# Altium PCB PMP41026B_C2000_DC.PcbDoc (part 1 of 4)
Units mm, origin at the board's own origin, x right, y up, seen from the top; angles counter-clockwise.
Board outline 100 x 30 mm, 4 copper layers (Top Layer, Layer2-Plane, Layer3-Plane, Bottom Layer), stack 1.565 mm thick; 260 components, 175 nets, 797 pads, 279 vias.
Unrouted connection lines stored in the file: 19.
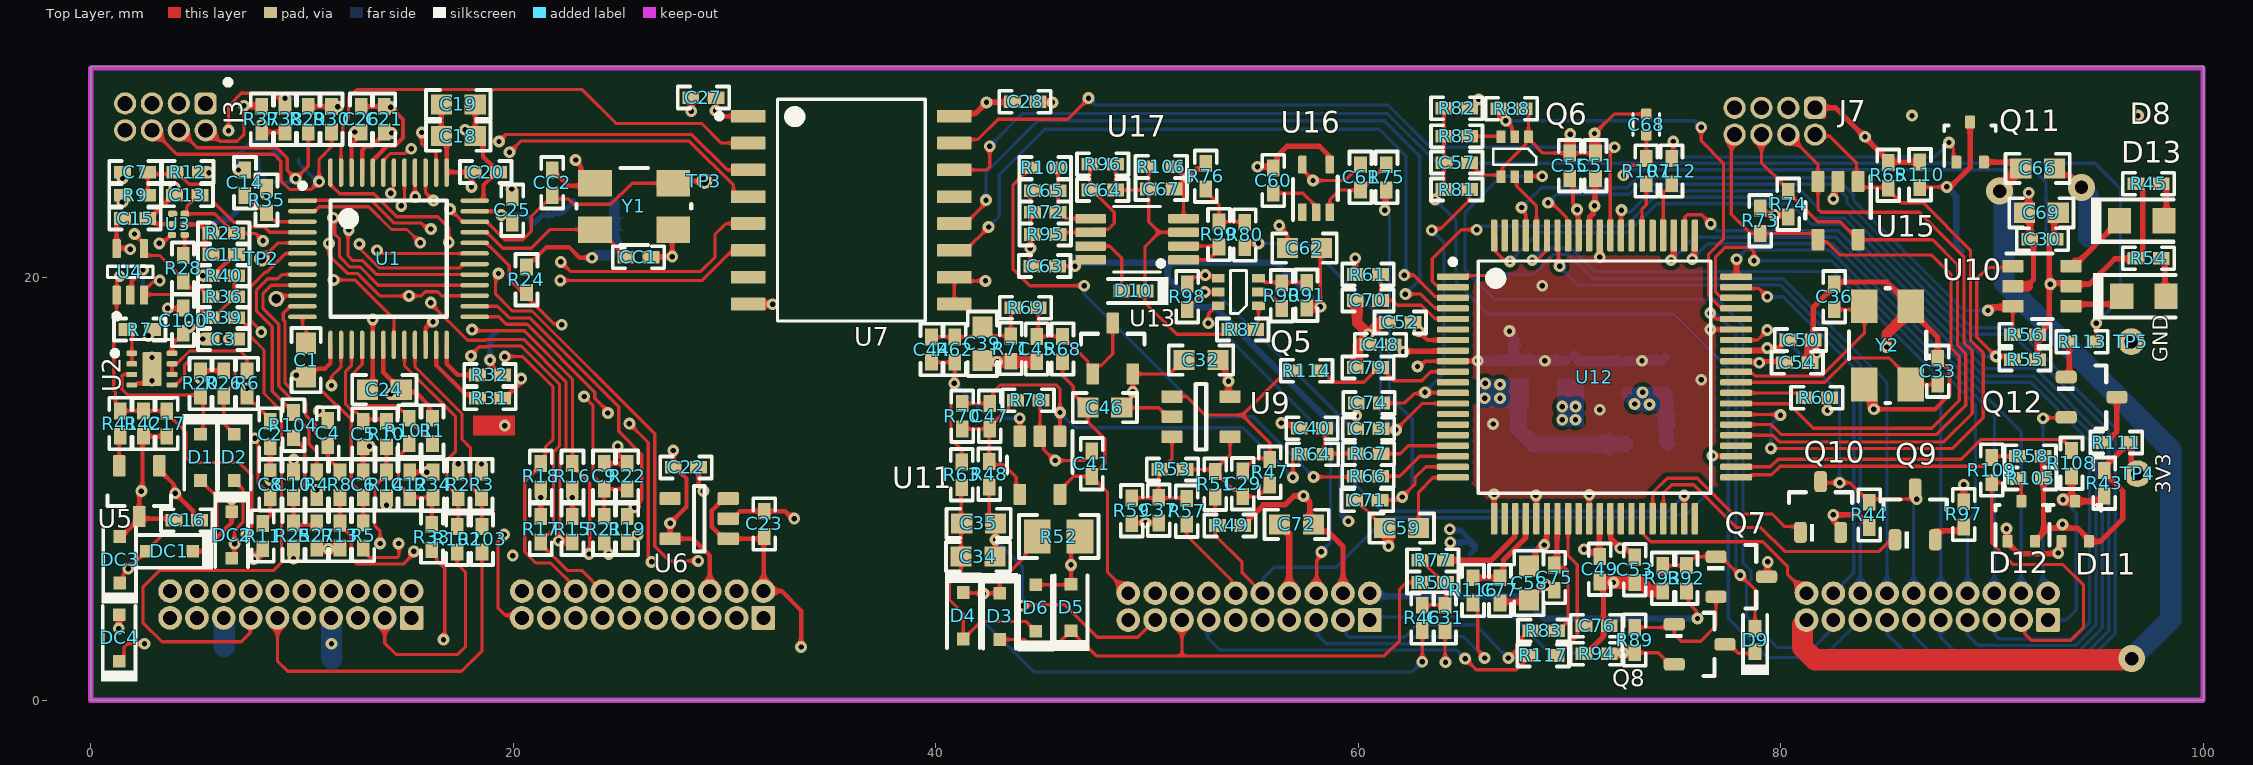
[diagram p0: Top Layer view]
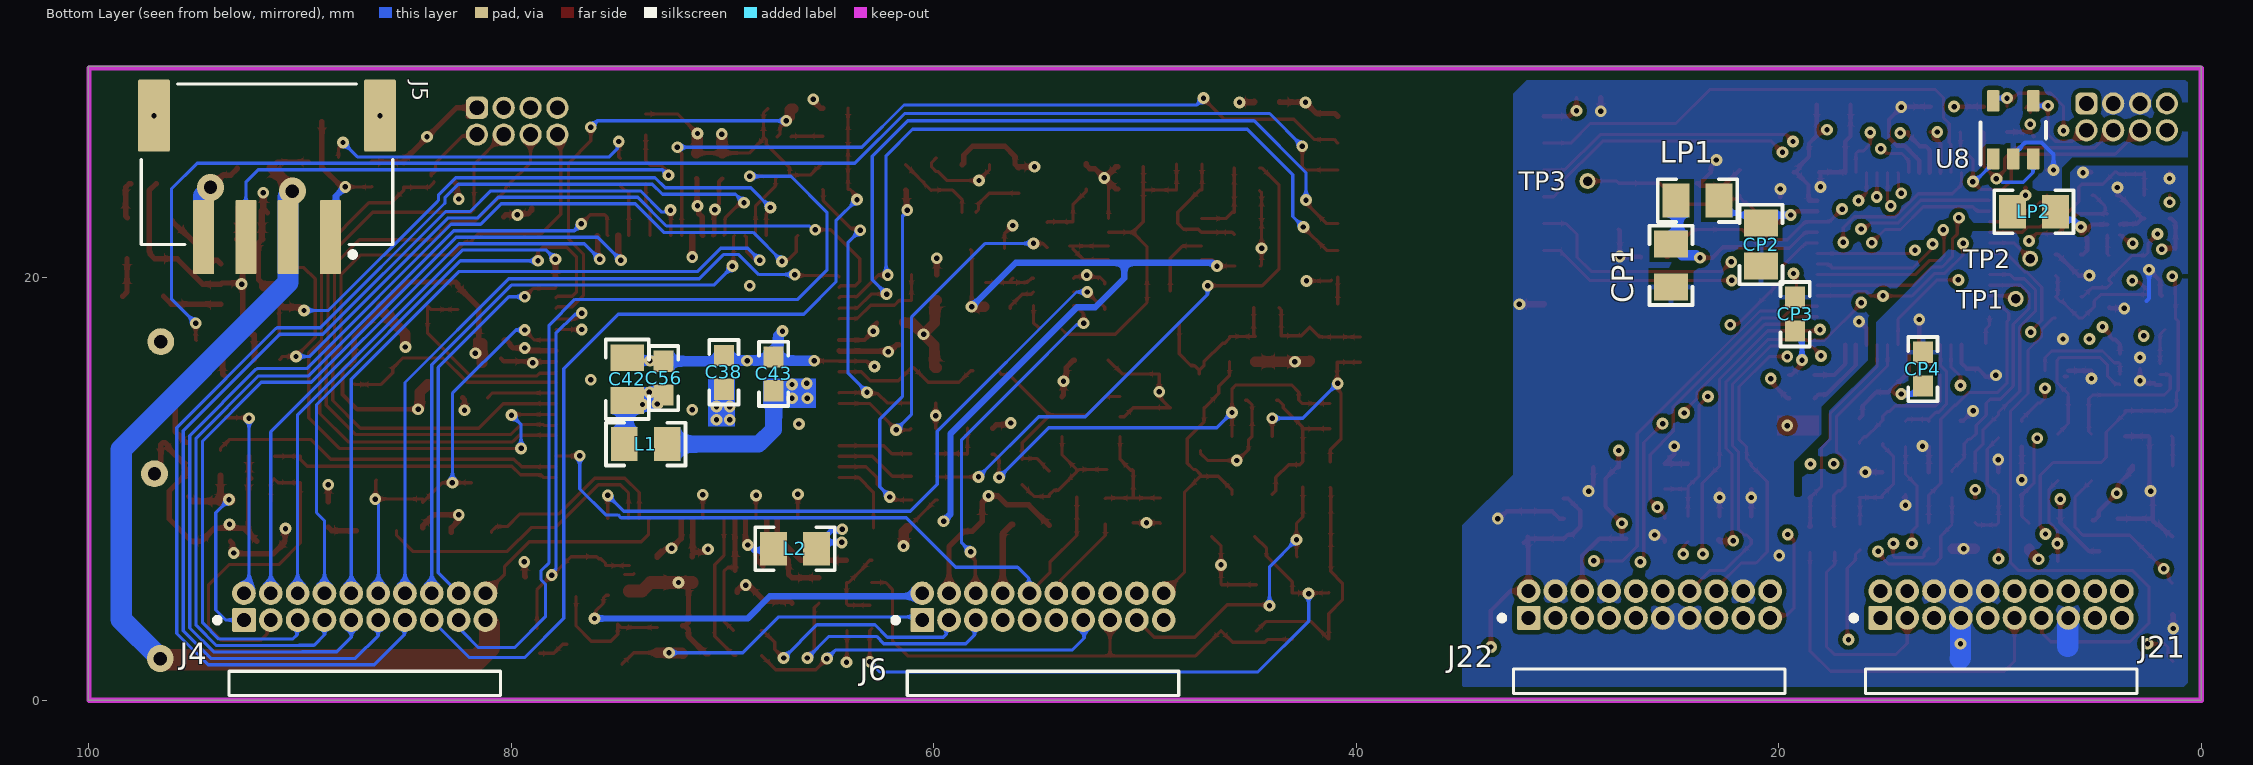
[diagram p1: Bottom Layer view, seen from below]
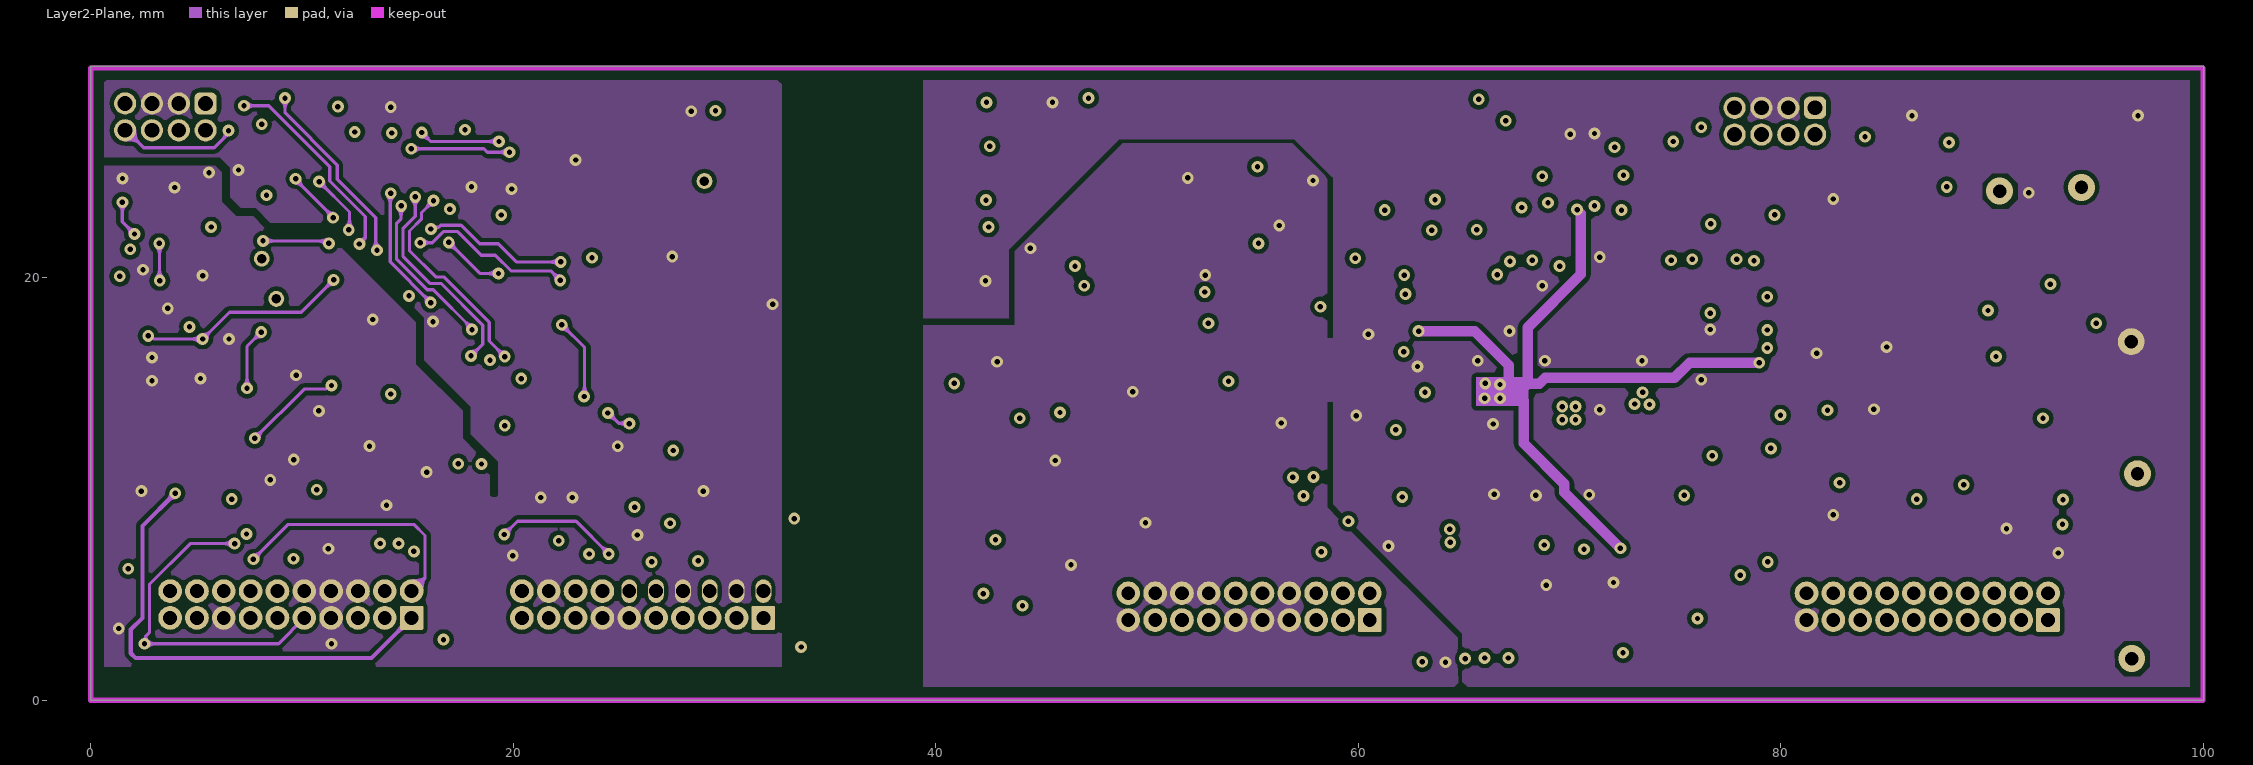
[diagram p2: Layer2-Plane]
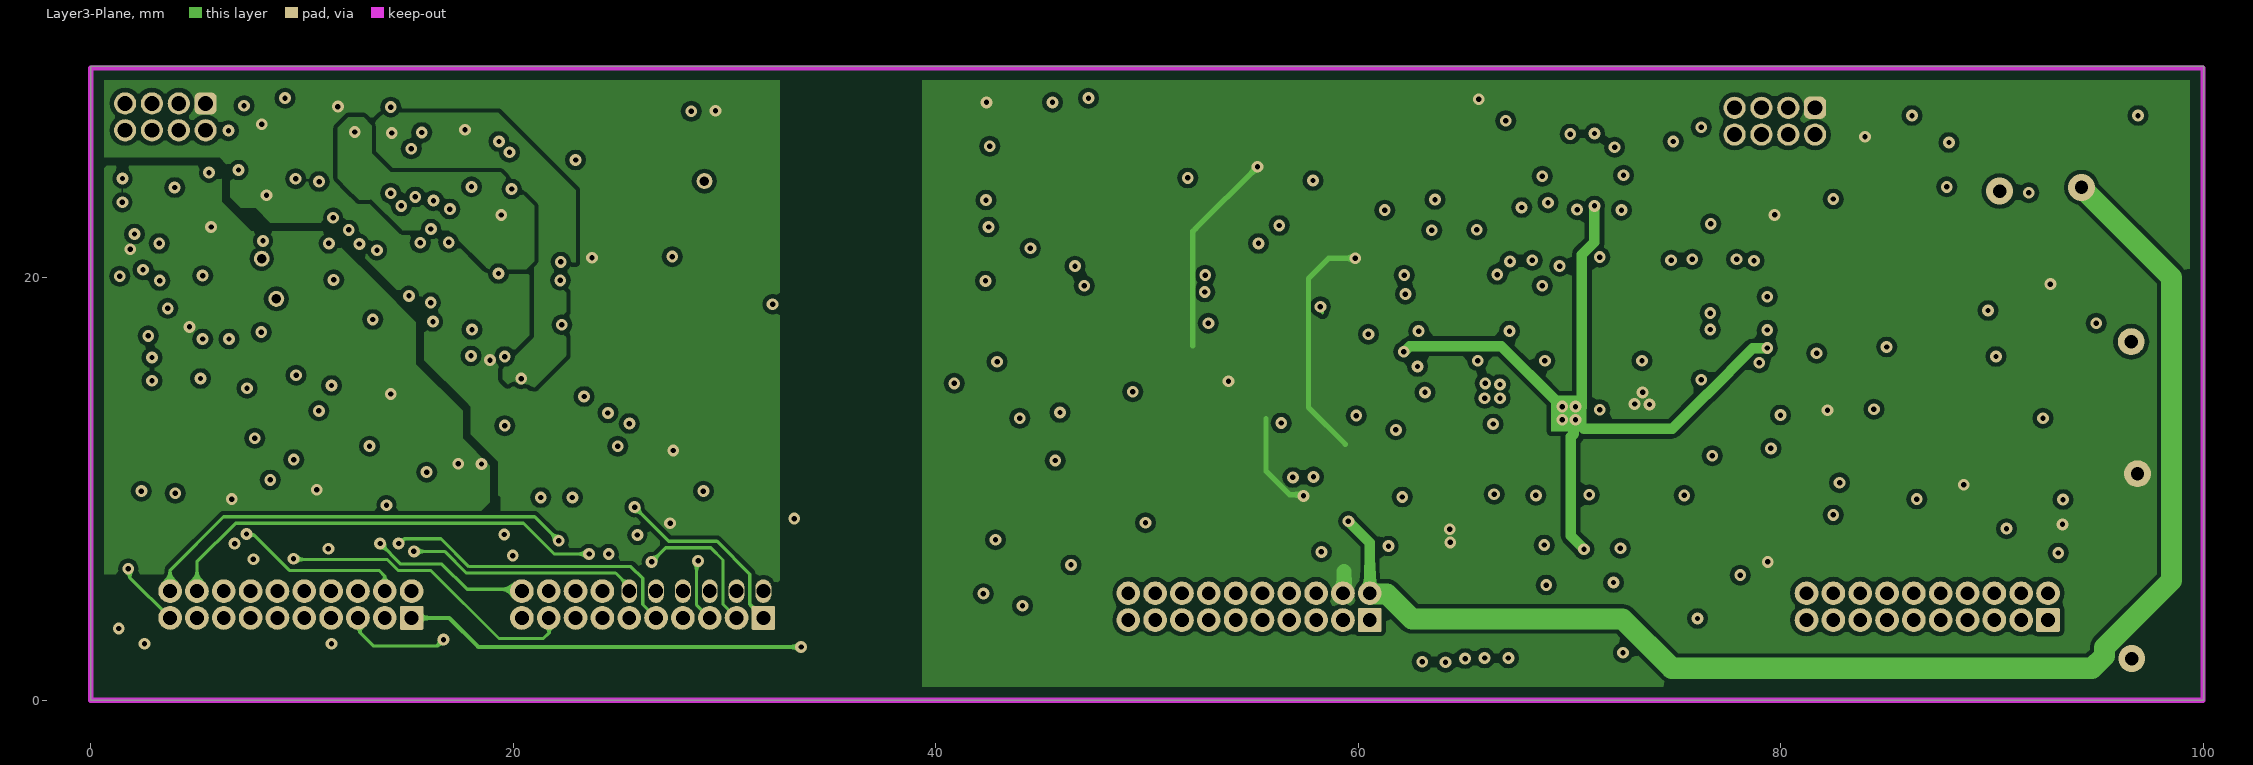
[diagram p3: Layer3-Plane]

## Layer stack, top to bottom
Top Solder: solder mask 0.0102, Solder Resist, Dk 3.5
Top Layer: signal copper 0.0356
Dielectric1: prepreg 0.2032, FR-4 High Tg, Dk 4.2
Layer2-Plane: signal copper 0.0356
Dielectric 2: core 1.016, FR-4 High Tg, Dk 4.2
Layer3-Plane: signal copper 0.0356
Dielectric 3: prepreg 0.2032, FR-4 High Tg, Dk 4.2
Bottom Layer: signal copper 0.0356
Bottom Solder: solder mask 0.0102, Solder Resist, Dk 3.5

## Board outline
0,0 0,30 100,30 100,0

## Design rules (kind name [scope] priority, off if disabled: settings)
AcuteAngle [All] p1: isadvanced=TRUE minimum=4.50000000000000E+0001 checktracksonly=FALSE
AssemblyTestPointUsage [All] p1: isadvanced=TRUE valid=2
AssemblyTestpoint [All] p1: isadvanced=TRUE testpointundercomponent=TRUE minsize=1.016 maxsize=2.54 preferedsize=1.524 minholesize=0 maxholesize=1.016 preferedholesize=0.813 testpointgrid=0.025 usegrid=TRUE gridtolerance=0 allowsidetop=TRUE allowsidebottom=TRUE
BoardOutlineClearance BoardOutlineClearance_MountingHoles [OnCopper and InComponentClass('Mounting Holes')] p1: isadvanced=TRUE gap=1 ignorepadtopadclearanceinfootprint=FALSE
BoardOutlineClearance BoardOutlineClearance_Poly [OnCopper and IsPoly] p2: isadvanced=TRUE gap=0.635 ignorepadtopadclearanceinfootprint=FALSE
BoardOutlineClearance [OnCopper and Not InComponentClass('Logo') and not InComponentClass('FiducialMark') and not InRegion(1000,500,4000,800) and not InPoly and not InComponent('J1')] p3: isadvanced=TRUE gap=1.016 ignorepadtopadclearanceinfootprint=FALSE
Clearance Clearance_Keepouts [((IsTrack Or IsArc) And Not InPoly) And IsFree and IsKeepOut vs ((IsTrack Or IsArc) And Not InPoly) And IsFree and IsKeepOut] p1: isadvanced=TRUE gap=0.152 ignorepadtopadclearanceinfootprint=FALSE except(0.178: Arc-THPad Track-THPad SMDPad-THPad THPad-THPad THPad-Via THPad-Fill THPad-Poly THPad-Region THPad-Text THPad-Hole)
Clearance Clearance_Poly [InPolygon] p2: isadvanced=TRUE gap=0.203 ignorepadtopadclearanceinfootprint=TRUE
Clearance Clearance_FiducialMark [IsKeepOut and InComponentClass('FiducialMark') vs IsPad and InComponentClass('FiducialMark')] p3: isadvanced=TRUE gap=0 ignorepadtopadclearanceinfootprint=FALSE
Clearance Clearance_1 [(ExistsOnLayer('Layer2-Plane') Or ExistsOnLayer('Layer3-Plane')) vs (ExistsOnLayer('Layer2-Plane') Or ExistsOnLayer('Layer3-Plane'))] p4: gap=0.152 ignorepadtopadclearanceinfootprint=TRUE except(0.178: Arc-THPad Track-THPad SMDPad-THPad THPad-THPad THPad-Via THPad-Fill THPad-Poly THPad-Region THPad-Text THPad-Hole) sourcerule=86 cellrowname=All cellrowtype=0 cellcolname=All cellcoltype=0 innerlayers=TRUE
Clearance Clearance_2 [(ExistsOnLayer('Top Layer') Or ExistsOnLayer('Bottom Layer')) vs (ExistsOnLayer('Top Layer') Or ExistsOnLayer('Bottom Layer'))] p5: gap=0.152 ignorepadtopadclearanceinfootprint=TRUE except(0.178: Arc-THPad Track-THPad SMDPad-THPad THPad-THPad THPad-Via THPad-Fill THPad-Poly THPad-Region THPad-Text THPad-Hole) sourcerule=86 cellrowname=All cellrowtype=0 cellcolname=All cellcoltype=0 outerlayers=TRUE
Clearance [All] p6: gap=0.152 ignorepadtopadclearanceinfootprint=TRUE except(0.178: Arc-THPad Track-THPad SMDPad-THPad THPad-THPad THPad-Via THPad-Fill THPad-Poly THPad-Region THPad-Text THPad-Hole) ismatrix=TRUE
ComponentClearance ComponentClearance_LP_Headers [HasFootprint('Samtec_SSQ-110-03-x-D') vs HasFootprint('FCI_89898-310ALF')] p1: isadvanced=TRUE gap=0 collisioncheckmode=3 verticalgap=2540 showdistances=FALSE // Exception for component clearance of LaunchPad Headers
ComponentClearance ComponentClearance_MountingHoles_FiducialMarks [InComponentClass('Mounting Holes') vs InComponentClass('FiducialMark')] p2: isadvanced=TRUE gap=1.27 collisioncheckmode=3 verticalgap=0.254 showdistances=FALSE
ComponentClearance ComponentClearance_Shunt [InComponentClass('Header') vs InComponentClass('Shunt')] p3: isadvanced=TRUE gap=0 collisioncheckmode=3 verticalgap=0 showdistances=FALSE
ComponentClearance ComponentClearance_Logo [InComponentClass('Logo')] p4: isadvanced=TRUE gap=1.27 collisioncheckmode=3 verticalgap=0.254 showdistances=FALSE
ComponentClearance ComponentClearance_ScrewToNut [(HasFootprint('NY PMS 440 0025 PH')) vs (HasFootprint('Keystone_1902C'))] p5: isadvanced=TRUE gap=0.127 collisioncheckmode=3 verticalgap=0.254 showdistances=FALSE
ComponentClearance ComponentClearance_MountingHoles [InComponentClass('Mounting Holes')] p6: isadvanced=TRUE gap=0.5 collisioncheckmode=3 verticalgap=2540 showdistances=FALSE
ComponentClearance ComponentClearance_SmallPassives [HasFootprint('0201*') or HasFootprint('0402*') or HasFootprint('0508') or HasFootprint('0603*') or HasFootprint('0612') or HasFootprint('0805*') or HasFootprint('0815*') or HasFootprint('0830*') or HasFootprint('1206*') or HasFootprint('1210*') or HasFootprint('1808*') or HasFootprint('1812*') or HasFootprint('1825*') or HasFootprint('2010*') or HasFootprint('2220*') or HasFootprint('2225*') or HasFootprint('2512*') or HasFootprint('2728*') or HasFootprint('3518*') vs HasFootprint('0201*') or HasFootprint('0402*') or HasFootprint('0508') or HasFootprint('0603*') or HasFootprint('0612') or HasFootprint('0805*') or HasFootprint('0815*') or HasFootprint('0830*') or HasFootprint('1206*') or HasFootprint('1210*') or HasFootprint('1808*') or HasFootprint('1812*') or HasFootprint('1825*') or HasFootprint('2010*') or HasFootprint('2220*') or HasFootprint('2225*') or HasFootprint('2512*') or HasFootprint('2728*') or HasFootprint('3518*')] p7: isadvanced=TRUE gap=0.076 collisioncheckmode=3 verticalgap=2540 showdistances=FALSE
ComponentClearance ComponentClearance_THtoSMT [IsThruComponent vs IsSMTComponent] p8: isadvanced=TRUE gap=0.254 collisioncheckmode=3 verticalgap=0.762 showdistances=FALSE
ComponentClearance ComponentClearance_THtoTH [IsThruComponent vs IsThruComponent] p9: isadvanced=TRUE gap=0.762 collisioncheckmode=3 verticalgap=0.762 showdistances=FALSE
ComponentClearance [All] p10: isadvanced=TRUE gap=0.127 collisioncheckmode=3 verticalgap=0.254 showdistances=FALSE
FabricationTestPointUsage TestPointUsage [All] p1: isadvanced=TRUE valid=2 allowmultiple=FALSE
FabricationTestpoint Testpoint [All] p1: isadvanced=TRUE side=3 testpointundercomponent=TRUE minsize=1.016 maxsize=2.54 preferedsize=1.524 minholesize=0 maxholesize=1.016 preferedholesize=0.813 testpointgrid=0.025 allowsidetop=TRUE allowsidebottom=TRUE usegrid=TRUE gridtolerance=0
FanoutControl Fanout_LCC [IsLCC] p1: isadvanced=TRUE bgadir=Out bgaviamode=Centered fanoutstyle=Auto fanoutdirection=Alternating viagrid=0.025 // Fanout_LCC (Default Rule)
FanoutControl Fanout_BGA [IsBGA] p2: isadvanced=TRUE bgadir=Out bgaviamode=Centered fanoutstyle=Auto fanoutdirection=Alternating viagrid=0.025 // Fanout_BGA (Default Rule)
FanoutControl Fanout_SOIC [IsSOIC] p3: isadvanced=TRUE bgadir=Out bgaviamode=Centered fanoutstyle=Auto fanoutdirection=Alternating viagrid=0.025 // Fanout_SOIC (Default Rule)
FanoutControl Fanout_Default [All] p4: isadvanced=TRUE bgadir=Out bgaviamode=Centered fanoutstyle=Auto fanoutdirection=Alternating viagrid=0.025 // Fanout_Default (Default Rule)
FanoutControl Fanout_Small [(CompPinCount < 5)] p5: isadvanced=TRUE bgadir=Out bgaviamode=Centered fanoutstyle=Auto fanoutdirection=OutThenIn viagrid=0.025 // Fanout_Small (Default Rule)
Height [All] p1: isadvanced=TRUE minheight=0 maxheight=25.4 prefheight=12.7
HoleSize [All] p1: isadvanced=TRUE absolutevalues=TRUE maxlimit=6.375 minlimit=0.2 maxpercent=80.000 minpercent=20.000
HoleToHoleClearance [All] p1: isadvanced=TRUE gap=0.254 allowstackedmicrovias=TRUE
LayerPairs [All] p1: isadvanced=TRUE enforce=TRUE
MinimumAnnularRing MinimumAnnularRing_ThermalPadVias [IsVia and InAnyComponent] p1: isadvanced=TRUE minimumring=0.127
MinimumAnnularRing [All] p2: isadvanced=TRUE minimumring=0.15
MinimumSolderMaskSliver MinimumSolderMaskSliver_Logo [InComponentClass('Logo') vs InComponentClass('Logo')] p1: isadvanced=TRUE minsoldermaskwidth=0.018
MinimumSolderMaskSliver [All] p2: isadvanced=TRUE minsoldermaskwidth=0.1
NetAntennae [All] p1: isadvanced=TRUE netantennaetolerance=0
PasteMaskExpansion [All] p1: isadvanced=TRUE expansion=0
PlaneClearance [All] p1: isadvanced=TRUE clearance=0.254
PlaneConnect [All] p1: isadvanced=TRUE planeconnectstyle=Relief reliefexpansion=0.254 reliefentries=4 reliefconductorwidth=0.31 reliefairgap=0.254
PolygonConnect [All] p1: thpad.connectstyle=Direct thpad.reliefconductorwidth=0.254 thpad.reliefentries=4 thpad.polygonreliefangle="90 Angle" thpad.airgapwidth=0.254 smdpad.connectstyle=Relief smdpad.reliefconductorwidth=0.254 smdpad.reliefentries=4 smdpad.polygonreliefangle="90 Angle" smdpad.airgapwidth=0.254 via.connectstyle=Direct via.reliefconductorwidth=0.254 via.reliefentries=4 via.polygonreliefangle="90 Angle" via.airgapwidth=0.254
RoutingCorners [All] p1: isadvanced=TRUE cornerstyle=45-Degree minsetback=2.54 maxsetback=2.54
RoutingPriority [All] p1: isadvanced=TRUE routingpriority=0
RoutingVias [All] p1: isadvanced=TRUE holewidth=0.3 width=0.6 viastyle="Through Hole" minholewidth=0.2 minwidth=0.5 maxholewidth=1 maxwidth=1.5
RoutingVias RoutingVias_2 [All] p2: holewidth=0.3 width=0.6 viastyle="Through Hole" minholewidth=0.3 minwidth=0.6 maxholewidth=0.3 maxwidth=0.6
ShortCircuit [All] p1: isadvanced=TRUE allowed=FALSE
SilkToBoardRegionClearance [Not ((IsComment or IsDesignator) And (Hide <> 'False')) and not InRegion(1000,500,4000,800)] p1:
SilkToSilkClearance SilkToSilkClearance_Pb-FreeLogo [(HasFootprint('Pb-Free_Overlay_Medium') OR HasFootprint('Pb-Free_Overlay_Small')) vs (HasFootprint('Pb-Free_Overlay_Medium') OR HasFootprint('Pb-Free_Overlay_Small'))] p1: isadvanced=TRUE silktosilkclearance=0
SilkToSilkClearance [All] p2: isadvanced=TRUE silktosilkclearance=0.076
SilkToSolderMaskClearance SilkToComponentPadClearance [(IsPad or IsFill or IsRegion) and InAnycomponent] p1: isadvanced=TRUE minsilkscreentomaskgap=0.076 clearancetoexposedcopper=TRUE
SilkToSolderMaskClearance "Silk to Solder Mask Opening" [All] p2: isadvanced=TRUE minsilkscreentomaskgap=0.076 clearancetoexposedcopper=FALSE
SolderMaskExpansion [All] p1: isadvanced=TRUE expansion=0.05 istentingtop=FALSE
SupplyNets "Schematic Supply Nets_27" [InNet('5Vp')] p1: isadvanced=TRUE voltage=0.000
SupplyNets "Schematic Supply Nets_26" [InNet('MCU_3V3')] p2: isadvanced=TRUE voltage=0.000
SupplyNets "Schematic Supply Nets_25" [InNet('S_MCU_A_3V3')] p3: isadvanced=TRUE voltage=0.000
SupplyNets "Schematic Supply Nets_24" [InNet('PGND')] p4: isadvanced=TRUE voltage=0.000
SupplyNets "Schematic Supply Nets_23" [InNet('3V0_ref')] p5: isadvanced=TRUE voltage=0.000
SupplyNets "Schematic Supply Nets_22" [InNet('S_3V3')] p6: isadvanced=TRUE voltage=0.000
SupplyNets "Schematic Supply Nets_21" [InNet('5V_SEC')] p7: isadvanced=TRUE voltage=0.000
SupplyNets "Schematic Supply Nets_20" [InNet('S_GND')] p8: isadvanced=TRUE voltage=0.000
SupplyNets "Schematic Supply Nets_19" [InNet('S_MCU_3V3')] p9: isadvanced=TRUE voltage=0.000
SupplyNets "Schematic Supply Nets_18" [InNet('S_MCU_1V2')] p10: isadvanced=TRUE voltage=0.000
SupplyNets "Schematic Supply Nets_17" [InNet('12VSB')] p11: isadvanced=TRUE voltage=0.000
SupplyNets "Schematic Supply Nets_16" [InNet('3V3A')] p12: isadvanced=TRUE voltage=0.000
SupplyNets "Schematic Supply Nets_15" [InNet('3V3')] p13: isadvanced=TRUE voltage=0.000
SupplyNets "Schematic Supply Nets_14" [InNet('MCU_1V2')] p14: isadvanced=TRUE voltage=0.000
SupplyNets "Schematic Supply Nets_13" [InNet('MCU_3V3')] p15: isadvanced=TRUE voltage=0.000
SupplyNets "Schematic Supply Nets_12" [InNet('3V3')] p16: isadvanced=TRUE voltage=0.000
SupplyNets "Schematic Supply Nets_11" [InNet('S_MCU_3V3')] p17: isadvanced=TRUE voltage=0.000
SupplyNets "Schematic Supply Nets_10" [InNet('PGND')] p18: isadvanced=TRUE voltage=0.000
SupplyNets "Schematic Supply Nets_9" [InNet('S_3V3')] p19: isadvanced=TRUE voltage=0.000
SupplyNets "Schematic Supply Nets_8" [InNet('5V_SEC')] p20: isadvanced=TRUE voltage=0.000
SupplyNets "Schematic Supply Nets_7" [InNet('12VSB')] p21: isadvanced=TRUE voltage=0.000
SupplyNets "Schematic Supply Nets_6" [InNet('3V0_ref')] p22: isadvanced=TRUE voltage=0.000
SupplyNets "Schematic Supply Nets_5" [InNet('MCU_1V2')] p23: isadvanced=TRUE voltage=0.000
SupplyNets "Schematic Supply Nets_4" [InNet('3V3A')] p24: isadvanced=TRUE voltage=0.000
SupplyNets "Schematic Supply Nets_3" [InNet('S_GND')] p25: isadvanced=TRUE voltage=0.000
SupplyNets "Schematic Supply Nets_2" [InNet('S_MCU_A_3V3')] p26: isadvanced=TRUE voltage=0.000
SupplyNets "Schematic Supply Nets_1" [InNet('S_MCU_1V2')] p27: isadvanced=TRUE voltage=0.000
SupplyNets "Schematic Supply Nets" [InNet('5Vp')] p28: isadvanced=TRUE voltage=0.000
UnRoutedNet [All] p1: isadvanced=TRUE checkbadconnections=TRUE
UnpouredPolygon [All] p1: isadvanced=TRUE
Width [All] p1: maxlimit=2 minlimit=0.152 preferedwidth=0.254 minimp=50.000000 maximp=50.000000 favimp=50.000000
3 further rules are at their usual default settings.

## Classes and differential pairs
component class Header: J3 J7
component class PMP41026B_C2000_DC_LLC_F280039C: C30 C33 C36 C38 C42 C43 C48 C49 C50 C51 C52 C53 C54 C55 C56 C58 C59 C70 C71 C73 C74 C75 C76 C77 C79 D8 D13 J7 L1 L2 R45 R54 R55 R56 R58 R60 R61 R65 R66 R67 R73 R74 R75 R77 R80 R81 R83 R114 R116 R117 TP4 TP5 U10 U12 U15 Y2
component class PMP41026B_C2000_DC_LLC_Control: C29 C31 C32 C34 C35 C37 C39 C40 C41 C44 C45 C46 C47 C57 C60 C61 C62 C63 C64 C65 C66 C67 C68 C69 C72 D3 D4 D5 D6 D9 D10 D11 D12 J4 J5 J6 Q5 Q6 Q7 Q8 Q9 Q10 Q11 Q12 R43 R44 R46 R47 R48 R49 R50 R51 R52 R53 R57 R59 R62 R63 R64 R68 R69 R70 R71 R72 R76 R78 R82 R85 R87 R88 R89 R90 R91 R92 R93 R94 R95 R96 R97 R98 R99 R100 R105 R106 R107 R108 R109 R110 R111 R112 R113 U9 U11 U13 U16 U17
component class PMP41026B_C2000_DC_PFC_2: C18 C19 C20 C21 C22 C23 C24 C25 C26 C27 C28 CP1 CP2 CP3 CP4 J3 Logo1 LP1 LP2 U1 U6 U7 U8 ZZ1 ZZ2 ZZ3
component class AssemblyNote: ZZ1 ZZ2 ZZ3
component class PMP41026B_C2000_DC_PFC_1: C1 C2 C3 C4 C5 C6 C7 C8 C9 C10 C11 C12 C13 C14 C15 C16 C17 C100 CC1 CC2 D1 D2 DC1 DC2 DC3 DC4 J21 J22 R1 R2 R3 R4 R5 R6 R7 R8 R9 R10 R11 R12 R13 R14 R15 R16 R17 R18 R19 R20 R21 R22 R23 R24 R25 R26 R27 R28 R29 R30 R31 R32 R33 R34 R35 R36 R37 R38 R39 R40 R41 R42 R101 R102 R103 R104 TP1 TP2 TP3 U2 U3 U4 U5 Y1
component class Logo: Logo1

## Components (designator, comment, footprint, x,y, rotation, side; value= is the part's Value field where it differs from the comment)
C1 "C0603C225K8PACTU" 0603 10.2,16.1 r90 top value=2.2uF
C2 "CGA2B2X7R1H471K050BA" 0402 8.5,12.6 r270 top value=470pF
C3 "CGA2B2X7R1H471K050BA" 0402 6.3,17.1 r0 top value=470pF
C4 "CGA2B2X7R1H471K050BA" 0402 11.225,12.65 r90 top value=470pF
C5 "CGA2B2X7R1H471K050BA" 0402 12.9,12.6 r270 top value=470pF
C6 "GRM155R60J104KA01D" 0402 12.9,10.2 r270 top value=0.1uF
C7 "C1005X5R1A473K050BA" 0402 2.1,25 r180 top value=0.047uF
C8 "04025U100CAT2A" 0402 8.5,10.2 r90 top value=10pF
C9 "GRM155R60J104KA01D" 0402 24.3,10.6 r270 top value=0.1uF
C10 "GRM155R61A102KA01D" 0402 9.6,10.2 r90 top value=1000pF
C11 "GRM155R71A104KA01D" 0402 6.3,21.1 r0 top value=0.1uF
C12 "GRM155R61A102KA01D" 0402 15.1,10.2 r90 top value=1000pF
C13 "GCM155R71C104KA55D" 0402 4.575,23.9 r180 top value=0.1uF
C14 "GRM155R60J104KA01D" 0402 7.3,24.5 r270 top value=0.1uF
C15 "GRM155R60J104KA01D" 0402 2.1,22.8 r180 top value=0.1uF
C16 "GCM155C71A474KE36D" 0402 4.55,8.525 r180 top value=0.47uF
C17 "GRM155R61A102KA01D" 0402 3.6,13.1 r270 top value=1000pF
C18 "GRM188R61A106ME69D" 0603 17.4,26.7 r180 top value=10uF
C19 "GRM188R61A106ME69D" 0603 17.4,28.2 r180 top value=10uF
C20 "GRM155R71A104KA01D" 0402 18.7,25 r0 top value=0.1uF
C21 "GRM155R71A104KA01D" 0402 13.9,27.5 r270 top value=0.1uF
C22 "GRM155R70J104KA01D" 0402 28.175,11.025 r0 top value=0.1uF
C23 "GRM155R71C104KA88D" 0402 31.875,8.35 r90 top value=0.1uF
C24 "C0603C225K8PACTU" 0603 13.9,14.7 r0 top value=2.2uF
C25 "GRM155R71A104KA01D" 0402 19.95,23.2 r90 top value=0.1uF
C26 "GRM155R71A104KA01D" 0402 12.8,27.5 r90 top value=0.1uF
C27 "GRM155R71A104KA01D" 0402 29,28.525 r0 top value=0.1uF
C28 "GRM155R71A104KA01D" 0402 44.225,28.325 r180 top value=0.1uF
C29 "GRM155R71H471KA01D" 0402 54.525,10.25 r90 top value=470pF
C30 "885012105010" 0402 92.375,21.825 r180 top value=0.1uF
C31 "GRM155R72A102KA01D" 0402 64.1,3.9 r270 top value=1000pF
C32 "GRM188R71E104KA01D" 0603 52.55,16.1 r0 top value=0.1uF
C33 "885012005056" 0402 87.425,15.575 r90 top value=15pF
C34 "C1608X7R1H334K080AC" 0603 42,6.8 r0 top value=0.33uF
C35 "C1608X7R1H334K080AC" 0603 42.025,8.375 r0 top value=0.33uF
C36 "885012005056" 0402 82.525,19.1 r90 top value=15pF
C37 "GRM155R71H471KA01D" 0402 50.55,9 r270 top value=470pF
C38 "GRM188R61A106ME69D" 0603 69.925,15.525 r270 bottom value=10uF
C39 "885012206076" 0603 42.2,16.875 r270 top value=1uF
C40 "CC0402KRX7R9BB101" 0402 57.8,12.875 r180 top value=100pF
C41 "CC0402KRX7R8BB104" 0402 47.375,11.2 r90 top value=0.1uF
C42 "LMK212ABJ106KG-T" 0805_HV 74.5,15.2 r270 bottom value=10uF
C43 "GRM188R61A106ME69D" 0603 67.575,15.45 r90 bottom value=10uF
C44 "CC0402KRX7R8BB104" 0402 39.8,16.6 r270 top value=0.1uF
C45 "GRM155R71E103KA01D" 0402 44.775,16.625 r270 top value=0.01uF
C46 "885012206076" 0603 48,13.85 r180 top value=1uF
C47 "CC0402KRX7R8BB104" 0402 42.55,13.45 r270 top value=0.1uF
C48 "885012105010" 0402 61.05,16.825 r180 top value=0.1uF
C49 "885012105010" 0402 71.425,6.2 r270 top value=0.1uF
C50 "885012105010" 0402 80.925,17.05 r0 top value=0.1uF
C51 "885012105010" 0402 71.225,25.3 r90 top value=0.1uF
C52 "885012105010" 0402 61.982,17.884 r180 top value=0.1uF
C53 "885012105010" 0402 73.075,6.175 r270 top value=0.1uF
C54 "885012105010" 0402 80.775,15.975 r0 top value=0.1uF
C55 "885012105010" 0402 70,25.3 r90 top value=0.1uF
C56 "CGA3E3X5R1A225K080AB" 0603 72.775,15.25 r270 bottom value=2.2uF
C57 "0402YC101KAT2A" 0402 64.65,25.45 r0 top value=100pF
C58 "CGA3E3X5R1A225K080AB" 0603 68.075,5.55 r90 top value=2.2uF
C59 "CGA3E3X5R1A225K080AB" 0603 62.05,8.15 r0 top value=2.2uF
C60 "GCM155R71E103KA37D" 0402 55.975,24.6 r270 top value=0.01uF
C61 "GCM155R71E103KA37D" 0402 60.1,24.75 r90 top value=0.01uF
C62 "GRM188Z71C225KE43" 0603 57.45,21.4 r180 top value=2.2uF
C63 "GRM155R71C104KA88D" 0402 45.15,20.55 r180 top value=0.1uF
C64 "0402YC101KAT2A" 0402 47.9,24.15 r0 top value=100pF
C65 "0402YC101KAT2A" 0402 45.175,24.125 r180 top value=100pF
C66 "GRM188R71E104KA01D" 0603 92.15,25.175 r180 top value=0.1uF
C67 "0402YC101KAT2A" 0402 50.675,24.2 r0 top value=100pF
C68 "885012205064" FP-885012205064_0402-MFG 73.625,27.25 r270 top value=3.3nF
C69 "GRM188R71E104KA01D" 0603 92.325,23.075 r0 top value=0.1uF
C70 "885012105010" 0402 60.45,18.925 r180 top value=0.1uF
C71 "CGA2B2X7R1H471K050BA" 0402 60.425,9.475 r0 top value=470pF
C72 "885012206076" 0603 57.075,8.325 r0 top value=1uF
C73 "CGA2B2X7R1H471K050BA" 0402 60.475,12.85 r0 top value=470pF
C74 "CGA2B2X7R1H471K050BA" 0402 60.5,14.075 r0 top value=470pF
C75 "CGA2B2X7R1H471K050BA" 0402 69.275,5.809 r90 top value=470pF
C76 "CGA2B2X7R1H471K050BA" 0402 71.275,3.525 r0 top value=470pF
C77 "CGA2B2X7R1H471K050BA" 0402 66.7,5.2 r270 top value=470pF
C79 "CGA2B2X7R1H471K050BA" 0402 60.45,15.75 r180 top value=470pF
C100 "GRM155R71A104KA01D" 0402 4.375,17.975 r90 top value=0.1uF
CC1 "885012005056" 0402 25.925,20.975 r0 top value=15pF
CC2 "885012005056" 0402 21.85,24.5 r90 top value=15pF
CP1 "LMK212ABJ106KG-T" 0805_HV 25.1,20.584 r90 bottom value=10uF
CP2 "LMK212ABJ106KG-T" 0805_HV 20.838,21.571 r90 bottom value=10uF
CP3 "CGA3E3X5R1A225K080AB" 0603 19.225,18.275 r270 bottom value=2.2uF
CP4 "CGA3E3X5R1A225K080AB" 0603 13.175,15.675 r270 bottom value=2.2uF
D1 "SDMK0340L-7-F" SOD-323 5.2,11.5 r270 top value=40V
D2 "SDMK0340L-7-F" SOD-323 6.8,11.5 r270 top value=40V
D3 "BAS316,115" SOD-323 43.025,3.975 r270 top value=100V
D4 "BAS316,115" SOD-323 41.3,4 r270 top value=100V
D5 "BAS316,115" SOD-323 46.4,4.4 r90 top value=100V
D6 "BAS316,115" SOD-323 44.725,4.375 r90 top value=100V
D8 "150080SS75000" WL-SMCW_RED_0805 97.075,22.7 r0 top value=Red
D9 "BAS516,115" SOD-523 78.775,2.85 r90 top value=100V
D10 "BAS516,115" SOD-523 49.35,19.375 r180 top value=100V
D11 "BAV99W,115" SOT-323 93.925,8.475 r90 top value=100V
D12 "BAV99W,115" SOT-323 91.375,8.475 r90 top value=100V
D13 "150080SS75000" WL-SMCW_RED_0805 97.175,19.125 r0 top value=Red
DC1 "SDMK0340L-7-F" SOD-323 3.725,7.05 r180 top value=40V
DC2 "SDMK0340L-7-F" SOD-323 6.675,7.824 r270 top value=40V
DC3 "SDMK0340L-7-F" SOD-323 1.375,6.65 r90 top value=40V
DC4 "SDMK0340L-7-F" SOD-323 1.35,2.95 r90 top value=40V
J3 "GRPB042MWCN-RC" Sullins_GRPB042MWCN 3.535,27.615 r270 top
J4 "M50-3901042" FP-M50-3901042_HDR20-MFG#1 86.925,0.8 r0 bottom
J5 "S4B-PH-SM4-TB" FP-S4B-PH-SM4-TB_CONN_HDR4-MFG 91.55,25.375 r180 bottom locked
J6 "M50-3901042" FP-M50-3901042_HDR20-MFG#1 54.825,0.8 r0 bottom
J7 "GRPB042MWCN-RC" Sullins_GRPB042MWCN 79.71,27.41 r270 top locked
J21 "M50-3901042" FP-M50-3901042_HDR20-MFG#1 9.475,0.9 r0 bottom
J22 "M50-3901042" FP-M50-3901042_HDR20-MFG#2 26.125,0.9 r0 bottom
L1 "BLM21PG221SN1D" 0805_HV 73.625,12.125 r180 bottom value="220 ohm"
L2 "742792063" 0805_HV 66.559,7.175 r0 bottom value="60 ohm"
Logo1 "CE Mark" CE_Mark_5mm 49.388,351.484 r0 top
LP1 "BLM21PG221SN1D" 0805_HV 23.85,23.65 r180 bottom value="220 ohm"
LP2 "742792063" 0805_HV 7.925,23.125 r180 bottom value="60 ohm"
Q5 "2N7002DW" SOT-363 54.325,19.325 r180 top value=60V
Q6 "2N7002DW" SOT-363 67.4,25.725 r270 top value=60V
Q7 "MMBT4401-7-F" SOT-23 78.125,5.85 r0 top value="40 V"
Q8 "MMBT4401-7-F" SOT-23 76.15,2.65 r0 top value="40 V"
Q9 "MMBT4403" SOT-23 86.35,8.8 r90 top value="40 V"
Q10 "MMBT4401-7-F" SOT-23 81.875,9.15 r90 top value="40 V"
Q11 "2N7002W-7-F" SOT-323 88.95,26.425 r90 top value=60V
Q12 "MMBT4401-7-F" SOT-23 94.7,14.35 r0 top value="40 V"
R1 "CRCW040210K0FKED" 0402 16.175,12.75 r90 top value=10.0k
R2 "CRCW040210K0FKED" 0402 17.4,10.2 r90 top value=10.0k
R3 "CRCW040210K0FKED" 0402 18.5,10.2 r90 top value=10.0k
R4 "CRCW040210K0FKED" 0402 10.7,10.2 r270 top value=10.0k
R5 "CRCW04020000Z0ED" 0402 12.9,7.8 r270 top value=0
R6 "CRCW04020000Z0ED" 0402 7.4,15 r90 top value=0
R7 "CRCW04020000Z0ED" 0402 2.325,17.55 r180 top value=0
R8 "CRCW04020000Z0ED" 0402 11.8,10.2 r270 top value=0
R9 "CRCW0402200RJNED" 0402 2.1,23.9 r180 top value=200
R10 "CRCW04020000Z0ED" 0402 14,12.6 r270 top value=0
R11 "CRCW04020000Z0ED" 0402 8.15,7.775 r270 top value=0
R12 "ERA-2AEB4871X" 0402 4.6,25 r180 top value=4.87k
R13 "CRCW040210K2FKED" 0402 11.8,7.8 r90 top value=10.2k
R14 "CRCW040210K2FKED" 0402 14,10.2 r90 top value=10.2k
R15 "CRCW040210K0JNED" 0402 22.8,8.1 r270 top value=10k
R16 "CRCW040210K0JNED" 0402 22.8,10.6 r90 top value=10k
R17 "CRCW040210K0JNED" 0402 21.3,8.1 r270 top value=10k
R18 "CRCW040210K0JNED" 0402 21.3,10.6 r90 top value=10k
R19 "CRCW040210K0JNED" 0402 25.4,8.1 r90 top value=10k
R20 "CRCW040222K6FKED" 0402 5.2,15 r270 top value=22.6k
R21 "CRCW04025K60JNED" 0402 24.3,8.1 r270 top value=5.6k
R22 "CRCW04027K50FKED" 0402 25.4,10.6 r270 top value=7.50k
R23 "CRCW040210K0JNED" 0402 6.3,22.1 r180 top value=10k
R24 "CRCW040210K0JNED" 0402 20.625,19.9 r90 top value=10k
R25 "CRCW04025K60JNED" 0402 9.6,7.8 r270 top value=5.6k
R26 "CRCW040222K6FKED" 0402 6.3,15 r270 top value=22.6k
R27 "CRCW04027K50FKED" 0402 10.7,7.8 r90 top value=7.50k
R28 "CRCW04028K66FKED" 0402 4.375,20.45 r270 top value=8.66k
R29 "CRCW040210K0JNED" 0402 10.3,27.5 r270 top value=10k
R30 "CRCW040210K0JNED" 0402 11.4,27.5 r270 top value=10k
R31 "CRCW04020000Z0ED" 0402 18.9,14.3 r0 top value=0
R32 "CRCW04020000Z0ED" 0402 18.9,15.4 r0 top value=0
R33 "CRCW04025K60JNED" 0402 16.15,7.725 r270 top value=5.6k
R34 "CRCW04027K50FKED" 0402 16.2,10.2 r270 top value=7.50k
R35 "CRCW04022K20JNED" 0402 8.325,23.675 r270 top value=2.2k
R36 "CRCW04028K66FKED" 0402 6.3,19.1 r180 top value=8.66k
R37 "CRCW04022K20JNED" 0402 8.1,27.5 r90 top value=2.2k
R38 "CRCW040210K0JNED" 0402 9.2,27.5 r270 top value=10k
R39 "CRCW04025K11FKED" 0402 6.3,18.1 r180 top value=5.11k
R40 "CRCW040210K0FKED" 0402 6.3,20.1 r180 top value=10.0k
R41 "CRCW040227K4FKED" 0402 1.4,13.1 r90 top value=27.4k
R42 "CRCW040222K6FKED" 0402 2.5,13.1 r270 top value=22.6k
R43 "RC1005F104CS" 0402 95.3,10.275 r90 top value=100k
R44 "ERJ-2RKF2003X" 0402 84.175,8.775 r90 top value=200k
R45 "CRCW0402820RJNED" 0402 97.4,24.45 r180 top value=820
R46 "RC0402FR-07100RL" 0402 63.025,3.9 r90 top value=100
R47 "CRCW04022K67FKED" 0402 55.8,10.8 r90 top value=2.67k
R48 "CRCW040210K0FKED" 0402 42.525,10.7 r90 top value=10.0k
R49 "CRCW040210K0FKED" 0402 53.925,8.275 r180 top value=10.0k
R50 "RC0402FR-07100RL" 0402 63.525,5.575 r0 top value=100
R51 "CRCW040251K1FKED" 0402 53.225,10.225 r90 top value=51.1k
R52 "RC0805JR-072R2L" 0805_HV 45.816,7.75 r180 top value=2.2
R53 "ERJ-2RKF1001X" 0402 51.2,10.925 r0 top value=1.00k
R54 "CRCW0402820RJNED" 0402 97.4,20.925 r180 top value=820
R55 "CRCW04021M50JNED" 0402 91.55,16.125 r0 top value=1.5Meg
R56 "CRCW04021M50JNED" 0402 91.55,17.3 r0 top value=1.5Meg
R57 "CRCW040251K1FKED" 0402 51.875,8.95 r90 top value=51.1k
R58 "CRCW040256K0JNED" 0402 91.8,11.55 r180 top value=56k
R59 "CRCW04022K67FKED" 0402 49.275,8.975 r90 top value=2.67k
R60 "CRCW040256K0JNED" 0402 81.7,14.325 r0 top value=56k
R61 "CRCW04022K20JNED" 0402 60.45,20.15 r180 top value=2.2k
R62 "CRCW040210K0FKED" 0402 40.9,16.6 r90 top value=10.0k
R63 "CRCW040210K0FKED" 0402 41.225,10.675 r90 top value=10.0k
R64 "RC0402FR-07100RL" 0402 57.825,11.65 r0 top value=100
R65 "CRCW04022K20JNED" 0402 85.075,24.85 r90 top value=2.2k
R66 "CRCW04020000Z0ED" 0402 60.45,10.6 r180 top value=0
R67 "CRCW04020000Z0ED" 0402 60.475,11.675 r180 top value=0
R68 "CRCW040210K0FKED" 0402 46,16.625 r90 top value=10.0k
R69 "CRCW04025K11FKED" 0402 44.25,18.575 r0 top value=5.11k
R70 "CRCW040210K0FKED" 0402 41.25,13.45 r90 top value=10.0k
R71 "RC0402FR-071KL" 0402 43.55,16.65 r90 top value=1.00k
R72 "CRCW0402510KJNED" 0402 45.175,23.1 r0 top value=510k
R73 "CRCW040210K0JNED" 0402 79.025,22.7 r270 top value=10k
R74 "CRCW040210K0JNED" 0402 80.35,23.475 r90 top value=10k
R75 "RC0402FR-07100RL" 0402 61.325,24.75 r90 top value=100
R76 "CRCW040210K0FKED" 0402 52.775,24.8 r270 top value=10.0k
R77 "CRCW04020000Z0ED" 0402 63.525,6.625 r180 top value=0
R78 "CRCW040210K0FKED" 0402 44.375,14.2 r180 top value=10.0k
R80 "RC0402FR-07100RL" 0402 54.625,22.025 r90 top value=100
R81 "RC0402FR-07100RL" 0402 64.65,24.175 r180 top value=100
R82 "RC1005F104CS" 0402 64.65,28.025 r0 top value=100k
R83 "RC0402FR-07100RL" 0402 68.775,3.3 r180 top value=100
R85 "ERJ-2RKF1203X" 0402 64.65,26.7 r180 top value=120k
R87 "MCR01MZPF10R0" 0402 54.525,17.55 r0 top value=10.0
R88 "RC1005F104CS" 0402 67.25,28 r180 top value=100k
R89 "CRCW040220R0FKED" 0402 73.075,2.85 r270 top value=20.0
R90 "CRCW040210K0JNED" 0402 56.375,19.15 r90 top value=10k
R91 "CRCW040210K0JNED" 0402 57.55,19.175 r270 top value=10k
R92 "CRCW040210K0JNED" 0402 75.525,5.775 r90 top value=10k
R93 "CRCW040210K0JNED" 0402 74.4,5.775 r90 top value=10k
R94 "RC0402FR-07820RL" 0402 71.275,2.2 r0 top value=820
R95 "CRCW040210K0FKED" 0402 45.175,22.05 r180 top value=10.0k
R96 "CRCW040222K1FKED" 0402 47.9,25.375 r0 top value=22.1k
R97 "CRCW04022K00FKED" 0402 88.65,8.8 r90 top value=2.00k
R98 "CRCW040210K0JNED" 0402 51.9,19.1 r90 top value=10k
R99 "CRCW040222K1FKED" 0402 53.4,22.05 r270 top value=22.1k
R100 "CRCW040256R0JNED" 0402 45.175,25.2 r0 top value=56
R101 "CRCW04020000Z0ED" 0402 15.075,12.75 r270 top value=0
R102 "CRCW04020000Z0ED" 0402 17.35,7.625 r270 top value=0
R103 "CRCW04020000Z0ED" 0402 18.525,7.625 r270 top value=0
R104 "CRCW04020000Z0ED" 0402 9.6,13.025 r270 top value=0
R105 "RC1005F104CS" 0402 91.825,10.5 r0 top value=100k
R106 "CRCW04025K11FKED" 0402 50.675,25.25 r180 top value=5.11k
R107 "CRCW04028K25FKED" 0402 73.625,25.05 r90 top value=8.25k
R108 "ERJ-2RKF1001X" 0402 93.75,11.225 r270 top value=1.00k
R109 "ERJ-2RKF1001X" 0402 89.975,10.9 r270 top value=1.00k
R110 "CRCW04025K11FKED" 0402 86.575,24.875 r270 top value=5.11k
R111 "RC0402FR-071KL" 0402 95.875,12.2 r0 top value=1.00k
R112 "ERJ-2RKF1001X" 0402 74.825,25.05 r270 top value=1.00k
R113 "CRCW040210K0FKED" 0402 94.25,16.975 r180 top value=10.0k
R114 "RC0402FR-07100RL" 0402 57.55,15.6 r180 top value=100
R116 "RC0402FR-07100RL" 0402 65.425,5.2 r270 top value=100
R117 "RC0402FR-07100RL" 0402 68.75,2.125 r180 top value=100
TP1 "TP_H0.45P0.75" TP_H045P075 8.788,18.999 r90 bottom
TP2 "TP_H0.45P0.75" TP_H045P075 8.094,20.904 r90 top
TP3 "TP_H0.45P0.75" TP_H045P075 29.05,24.575 r90 top
TP4 "3V3" TP_50MIL-25MILHOLE 96.875,10.725 r0 top
TP5 "GND" TP_50MIL-25MILHOLE 96.575,16.975 r0 top
U1 "F280023PTSR" PT0048A-IPC_C 14.1,20.9 r0 top
U2 "OPA2991IDSGR" DSG0008A-MFG 2.9,15.675 r0 top locked
U3 "SN74LVC1G3157DRYR" DRY0006A 4.15,22.525 r0 top
U4 "OPA991IDCKR" DCK0005A-MFG 1.875,20.275 r90 top
U5 "REF3030AIDBZR" DBZ0003A_N 2.3,9.9 r270 top
U6 "TLV71333PDBVR" DBV0005A_N 28.8,8.6 r180 top
U7 "ISO7762FDWR" DW0016B-MFG 36,23.2 r0 top
U8 "ESDS314DBVR" DBV0005A_N 8.9,27 r90 bottom
U9 "TLV376IDBVR" DBV0005A_N 52.55,13.425 r0 top
U10 "SN74LVC2G07DBVR" DBV0006A_N 92.35,19.6 r0 top
U11 "OPA365" DBV0005A_N 44.925,11.125 r270 top
U12 "F280039CPNQ1" PN0080A-MFG 71.175,15.3 r0 top locked
U13 "TLVH431BQDBZR" DBZ0003A_N 48.375,16.65 r90 top
U15 "ESDS314DBVR" DBV0005A_N 82.7,23.175 r270 top
U16 "LM20BIM7X/NOPB" DCK0005A_N 58,24.225 r90 top
U17 "OPA2991IDGKR" DGK0008A-MFG 49.525,21.825 r180 top
Y1 "ECS-200-18-30B-AGN-TR" ECS_ECX-53B 25.725,23.375 r90 top
Y2 "ECS-200-18-30B-AGN-TR" ECS_ECX-53B 85.05,16.8 r180 top
ZZ1 "These assemblies are ESD sensitive, ESD precautions shall be observed." AssemblyNote 1.275,141.137 r0 top
ZZ2 "These assemblies must be clean and free from flux and all contaminants. Use of no clean flux is not acceptable." AssemblyNote 1.275,138.888 r0 top
ZZ3 "These assemblies must comply with workmanship standards IPC-A-610 Class 2, unless otherwise specified." AssemblyNote 1.275,136.638 r0 top

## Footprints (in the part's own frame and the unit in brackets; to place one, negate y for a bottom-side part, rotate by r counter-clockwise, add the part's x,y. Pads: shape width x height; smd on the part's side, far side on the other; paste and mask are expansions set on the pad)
0402 [mm] "0402 from SM-752 data"
  rect 0.8x0.6 smd: 1(-0.6,0) 2(0.6,0)
  silkscreen extent -1.22,-0.52 1.22,0.52, body extent -0.55,-0.3 0.55,0.3, height 0.6
0603 [mm] "0603 from SM-752 data"
  rect 1x0.95 smd: 1(-0.8,0) 2(0.8,0)
  silkscreen extent -1.52,-0.69 1.52,0.69, body extent -0.87,-0.47 0.87,0.47, height 1
0805_HV [mil] "0805 with 30mil clearance between pads"
  rect 50x63 smd: 1(-40,0) 2(40,0)
  silkscreen extent -74,-40 74,40, body extent -43,-29 43,29, height 57
AssemblyNote [mm] "Assembly Note"
CE_Mark_5mm [mm] "Minimum text height for CE Mark"
  silkscreen extent -3.5,-2.5 3.5,2.5
DBV0005A_N [mm] "SOT23, 5-Leads, Body 2.9x1.6mm, Pitch 0.95mm, Lead Span 2.8mm, IPC Medium Density"
  rrect17% 1x0.6 smd: 1(-1.375,0.95) 2(-1.375,0) 3(-1.375,-0.95) 4(1.375,-0.95) 5(1.375,0.95)
  silkscreen extent -0.25,-1.55 0.25,1.55, body extent -1.42,-1.46 1.42,1.46, height 1.09
DBV0006A_N [mm] "SOT23, 6-Leads, Body 2.9x1.6mm, Pitch 0.95mm, Lead Span 2.8mm, IPC Medium Density"
  rrect17% 1x0.6 smd: 1(-1.375,0.95) 2(-1.375,0) 3(-1.375,-0.95) 4(1.375,-0.95) 5(1.375,0) 6(1.375,0.95)
  silkscreen extent -1.68,-1.55 0.5,1.55, body extent -1.42,-1.46 1.42,1.46, height 1.12
DBZ0003A_N [mm] "SOT23, 3-Leads, Body 2.9x1.3mm, Pitch 0.95mm, Lead Span 2.4mm, IPC Medium Density"
  rrect17% 1x0.6 smd: 1(-1.2,0.95) 2(-1.2,-0.95) 3(1.2,0)
  silkscreen extent 0.2,-1.5 0.7,1.5, body extent -1.26,-1.46 1.26,1.46, height 0.98
DCK0005A-MFG [mm]
  rrect25% 0.9x0.4 smd paste-1000 mask+0: 1(-1.1,0.65) 2(-1.1,0) 3(-1.1,-0.65) 4(1.1,-0.65) 5(1.1,0.65)
  silkscreen extent -2.22,-1.07 0.27,1.07, body extent -1.65,-1.33 1.65,1.33, height 0.25
DCK0005A_N [mm] "SOT353, 5-Leads, Body 2x1.3mm, Pitch 0.65mm, Lead Span 2.1mm, IPC Medium Density"
  rrect25% 0.85x0.4 smd: 1(-1.125,0.65) 2(-1.125,0) 3(-1.125,-0.65) 4(1.125,-0.65) 5(1.125,0.65)
  silkscreen extent -1.48,-1.02 0.55,1.1, body extent -1.14,-1 1.14,1, height 0.95
DGK0008A-MFG [mm]
  rrect22% 1.45x0.45 smd paste+0 mask+0: 1(-2.2,0.975) 2(-2.2,0.325) 3(-2.2,-0.325) 4(-2.2,-0.975) 5(2.2,-0.975) 6(2.2,-0.325) 7(2.2,0.325) 8(2.2,0.975)
  silkscreen extent -1.25,-1.55 1.1,1.55, body extent -2.45,-1.5 2.45,1.5, height 1.1
DRY0006A [mm] "USON-6"
  rrect67% 0.45x0.3 smd paste-0.05 mask-0.05: 1(-0.275,0.5)
  rrect67% 0.4x0.3 smd paste-0.05 mask-0.05: 2(-0.3,0) 3(-0.3,-0.5) 4(0.3,-0.5) 5(0.3,0) 6(0.3,0.5)
  body extent -0.5,-0.72 0.5,0.73, height 0.58
DSG0008A-MFG [mm]
  rrect40% 0.5x0.25 smd paste+0 mask+0: 1(-0.95,0.75) 2(-0.95,0.25) 3(-0.95,-0.25) 4(-0.95,-0.75) 5(0.95,-0.75) 6(0.95,-0.25) 7(0.95,0.25) 8(0.95,0.75)
  rrect11% 0.9x1.6 smd paste-1000 mask+0: 9(0,0)
  silkscreen extent -1.87,-1.39 1,1.4, body extent -1.3,-1.15 1.3,1.15, height 0.25
DW0016B-MFG [mm]
  rrect17% 1.65x0.6 smd paste+0 mask+0: 1(-4.875,4.445) 2(-4.875,3.175) 3(-4.875,1.905) 4(-4.875,0.635) 5(-4.875,-0.635) 6(-4.875,-1.905) 7(-4.875,-3.175) 8(-4.875,-4.445) 9(4.875,-4.445) 10(4.875,-3.175) 11(4.875,-1.905) 12(4.875,-0.635) 13(4.875,0.635) 14(4.875,1.905) 15(4.875,3.175) 16(4.875,4.445)
  silkscreen extent -6.37,-5.25 3.5,5.25, body extent -5.8,-5.5 5.8,5.5, height 0.25
ECS_ECX-53B [mm] "SMD, 4-Leads, Body 5x3.2mm"
  rect 1.25x1.6 smd: 1(-1.1,1.85) 2(-1.1,-1.85) 3(1.1,-1.85) 4(1.1,1.85)
  silkscreen extent -2.05,-2.7 1.83,2.73, body extent -1.7,-2.6 1.7,2.6, height 0.86
FP-885012205064_0402-MFG [mm]
  rrect20% 0.5x0.5 smd paste+0 mask+0: 1(-0.5,0) 2(0.5,0)
  silkscreen extent -0.53,-0.63 0.53,0.63, body extent -0.5,-0.25 0.5,0.25, height 0.55
FP-M50-3901042_HDR20-MFG#1 [mm]
  rrect9% 1.12x1.12 hole 0.65 paste-2539.97 mask+0: 1(5.715,-3)
  round 1.12 hole 0.65 paste-2539.97 mask+0: 2(5.715,-4.27) 3(4.445,-3) 4(4.445,-4.27) 5(3.175,-3) 6(3.175,-4.27) 7(1.905,-3) 8(1.905,-4.27) 9(0.635,-3) 10(0.635,-4.27) 11(-0.635,-3) 12(-0.635,-4.27) 13(-1.905,-3) 14(-1.905,-4.27) 15(-3.175,-3) 16(-3.175,-4.27) 17(-4.445,-3) 18(-4.445,-4.27) 19(-5.715,-3) 20(-5.715,-4.27)
  silkscreen extent -6.43,-3.12 7.1,0.58, body extent -6.35,-4.47 6.35,4.3, height 3.55
FP-M50-3901042_HDR20-MFG#2 [mm]
  rrect9% 1.12x1.12 hole 0.65 paste-2539.97 mask+0: 1(5.715,-3)
  round 1.12 / inner oval 0.75x1.12 / far side round 1.12 hole 0.65 paste-2539.97 mask+0: 2(5.715,-4.27) 4(4.445,-4.27) 6(3.175,-4.27) 8(1.905,-4.27) 10(0.635,-4.27) 12(-0.635,-4.27)
  round 1.12 hole 0.65 paste-2539.97 mask+0: 3(4.445,-3) 5(3.175,-3) 7(1.905,-3) 9(0.635,-3) 11(-0.635,-3) 13(-1.905,-3) 14(-1.905,-4.27) 15(-3.175,-3) 16(-3.175,-4.27) 17(-4.445,-3) 18(-4.445,-4.27) 19(-5.715,-3) 20(-5.715,-4.27)
  silkscreen extent -6.43,-3.12 7.1,0.58, body extent -6.35,-4.47 6.35,4.3, height 3.55
FP-S4B-PH-SM4-TB_CONN_HDR4-MFG [mm]
  rrect10% 1x3.5 smd paste+0 mask+0: 1(3,-3.45) 2(1,-3.45) 3(-1,-3.45) 4(-3,-3.45)
  rrect7% 1.5x3.4 smd paste+0 mask+0: 5(-5.35,2.3) 6(5.35,2.3)
  silkscreen extent -5.95,-4.4 5.95,3.8, body extent -5.95,-4.8 5.95,3.8, height 5.6
PN0080A-MFG [mm]
  rrect33% 1.5x0.3 smd paste+0 mask+0: 1(-6.7,4.75) 2(-6.7,4.25) 3(-6.7,3.75) 4(-6.7,3.25) 5(-6.7,2.75) 6(-6.7,2.25) 7(-6.7,1.75) 8(-6.7,1.25) 9(-6.7,0.75) 10(-6.7,0.25) 11(-6.7,-0.25) 12(-6.7,-0.75) 13(-6.7,-1.25) 14(-6.7,-1.75) 15(-6.7,-2.25) 16(-6.7,-2.75) 17(-6.7,-3.25) 18(-6.7,-3.75) 19(-6.7,-4.25) 20(-6.7,-4.75) 41(6.7,-4.75) 42(6.7,-4.25) 43(6.7,-3.75) 44(6.7,-3.25) 45(6.7,-2.75) 46(6.7,-2.25) 47(6.7,-1.75) 48(6.7,-1.25) 49(6.7,-0.75) 50(6.7,-0.25) 51(6.7,0.25) 52(6.7,0.75) 53(6.7,1.25) 54(6.7,1.75) 55(6.7,2.25) 56(6.7,2.75) 57(6.7,3.25) 58(6.7,3.75) 59(6.7,4.25) 60(6.7,4.75)
  rrect33% 0.3x1.5 smd paste+0 mask+0: 21(-4.75,-6.7) 22(-4.25,-6.7) 23(-3.75,-6.7) 24(-3.25,-6.7) 25(-2.75,-6.7) 26(-2.25,-6.7) 27(-1.75,-6.7) 28(-1.25,-6.7) 29(-0.75,-6.7) 30(-0.25,-6.7) 31(0.25,-6.7) 32(0.75,-6.7) 33(1.25,-6.7) 34(1.75,-6.7) 35(2.25,-6.7) 36(2.75,-6.7) 37(3.25,-6.7) 38(3.75,-6.7) 39(4.25,-6.7) 40(4.75,-6.7) 61(4.75,6.7) 62(4.25,6.7) 63(3.75,6.7) 64(3.25,6.7) 65(2.75,6.7) 66(2.25,6.7) 67(1.75,6.7) 68(1.25,6.7) 69(0.75,6.7) 70(0.25,6.7) 71(-0.25,6.7) 72(-0.75,6.7) 73(-1.25,6.7) 74(-1.75,6.7) 75(-2.25,6.7) 76(-2.75,6.7) 77(-3.25,6.7) 78(-3.75,6.7) 79(-4.25,6.7) 80(-4.75,6.7)
  silkscreen extent -6.82,-5.5 5.5,5.57, body extent -7.55,-7.55 7.55,7.55, height 0.25
PT0048A-IPC_C [mm]
  rrect47% 1.355x0.212 smd paste+0 mask+0: 1(-4.075,2.75)
  rrect100% 1.355x0.212 smd paste+0 mask+0: 2(-4.075,2.25) 3(-4.075,1.75) 4(-4.075,1.25) 5(-4.075,0.75) 6(-4.075,0.25) 7(-4.075,-0.25) 8(-4.075,-0.75) 9(-4.075,-1.25) 10(-4.075,-1.75) 11(-4.075,-2.25) 12(-4.075,-2.75) 25(4.075,-2.75) 26(4.075,-2.25) 27(4.075,-1.75) 28(4.075,-1.25) 29(4.075,-0.75) 30(4.075,-0.25) 31(4.075,0.25) 32(4.075,0.75) 33(4.075,1.25) 34(4.075,1.75) 35(4.075,2.25) 36(4.075,2.75)
  rrect100% 0.212x1.355 smd paste+0 mask+0: 13(-2.75,-4.075) 14(-2.25,-4.075) 15(-1.75,-4.075) 16(-1.25,-4.075) 17(-0.75,-4.075) 18(-0.25,-4.075) 19(0.25,-4.075) 20(0.75,-4.075) 21(1.25,-4.075) 22(1.75,-4.075) 23(2.25,-4.075) 24(2.75,-4.075) 37(2.75,4.075) 38(2.25,4.075) 39(1.75,4.075) 40(1.25,4.075) 41(0.75,4.075) 42(0.25,4.075) 43(-0.25,4.075) 44(-0.75,4.075) 45(-1.25,4.075) 46(-1.75,4.075) 47(-2.25,4.075) 48(-2.75,4.075)
  silkscreen extent -4.2,-2.75 2.75,3.58, body extent -4.85,-4.85 4.85,4.85, height 0.25
SOD-323 [mm] "NXP recommended land pattern"
  rect 0.6x0.6 smd paste-0.05: 1(-1.1,0) 2(1.1,0)
  silkscreen extent -2.06,-0.86 1.53,0.86, body extent -1.3,-0.67 1.3,0.68, height 1.1
SOD-523 [mm] "NXP Semiconductor recommended land pattern, nominal STEP model"
  rect 0.8x0.6 smd paste-0.05: 1(-0.55,0) 2(0.55,0)
  silkscreen extent -1.65,-0.66 1.2,0.66, body extent -0.8,-0.4 0.8,0.4, height 0.72
SOT-23 [mm] "SOT23, 3-Leads, Body 2.9x1.3mm, Pitch 0.95mm, Lead Span 2.5mm, IPC Medium Density"
  rrect50% 1x0.6 smd: 1(-1.2,0.95) 2(-1.2,-0.95) 3(1.2,0)
  silkscreen extent -1.62,-1.5 0.7,1.5, body extent -1.16,-1.45 1.21,1.45, height 1
SOT-323 [mm] "Diodes Inc recommended land pattern.  2016-02-24"
  rrect21% 0.6x0.47 smd: 1(-0.95,0.65) 2(-0.95,-0.65) 3(0.95,0)
  silkscreen extent -1.14,-1.22 0.77,1.22, body extent -1.13,-1.13 1.12,1.12, height 1.13
SOT-363 [mm]
  rect 0.6x0.42 smd mask+0.051: 1(-0.95,0.65) 2(-0.95,0) 3(-0.95,-0.65) 4(0.95,-0.65) 5(0.95,0) 6(0.95,0.65)
  silkscreen extent -0.38,-1.02 0.38,1.02, body extent -1.1,-1.1 1.1,1.1, height 1.12
Sullins_GRPB042MWCN [mm] "Header, 1.27mm, 4x2, R/A, TH"
  rrect50% 1.05x1.05 hole 0.7: 1(-0.635,1.905)
  round 1.05 hole 0.7: 2(0.635,1.905) 3(-0.635,0.635) 4(0.635,0.635) 5(-0.635,-0.635) 6(0.635,-0.635) 7(-0.635,-1.905) 8(0.635,-1.905)
  body extent -5.28,-2.54 0.84,2.54, height 3.4
TP_50MIL-25MILHOLE [mm]
  round 1.27 hole 0.635: 1(0,0)
TP_H045P075 [mm] "TP_H0.45P0.75"
  round 0.75 hole 0.45: 1(0,0)
WL-SMCW_RED_0805 [mm] "SMD, 2-Leads, Body 1.6x0.8mm"
  rect 1.1x1.2 smd: 1(-1.05,0) 2(1.05,0)
  silkscreen extent -2.4,-1.1 1.5,1.1, body extent -1,-0.62 1,0.63, height 0.7

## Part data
C1 C24: library part CMP-0006906-5, "CAP, CERM, 2.2 uF, 10 V, +/- 10%, X5R, 0603", Cap_Case=0603, Manufacturer=Kemet, Supplier Part Number 1=399-4911-1-ND, TempCo=X5R, Tolerance_%=10%, Value1=Unknown, Value2=10V, ValueDisplayed=2.2uF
